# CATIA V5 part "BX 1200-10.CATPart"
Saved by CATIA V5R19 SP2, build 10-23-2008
Part number: BX 1200-10
Bounding box of the stored display mesh (mm): x -59.975 to 59.975, y -59.975 to 59.975, z 0 to 100
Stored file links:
  C:\Users\Bora\Desktop\3D Katı model\BX serisi\BX 1200\BX 1200-10.CATPart
  C:\Program Files\Dassault Systemes\B19\intel_a\reffiles\standard\MetricThickPitch.txt
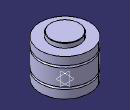
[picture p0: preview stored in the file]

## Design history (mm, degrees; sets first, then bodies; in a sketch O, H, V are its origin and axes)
Body1 (main body)
  Sketch1 on yz-plane, origin (0, 0, 0), H (0, 1, 0), V (0, 0, 1)
    point P2 (60, 20)
    line L1 (60, 20) -> (60, 0)
    point P3 (60, 25)
    point P4 (60, 65)
    line L2 (60, 65) -> (60, 25)
    point P6 (35, 99)
    arc A1 centre (34, 99) radius 1 from (35, 99) to (34, 100) ccw
    point P8 (35, 99)
    line L3 (35, 99) -> (35, 89)
    point P9 (60, 70)
    line L4 (60, 89) -> (60, 70)
    point P11 (60, 20)
    point P12 (60, 25)
    arc A2 centre (60, 22.5) radius 2.5 from (60, 25) to (60, 20) ccw
    point P13 (60, 65)
    point P14 (60, 70)
    arc A3 centre (60, 67.5) radius 2.5 from (60, 70) to (60, 65) ccw
    line L5 (34, 100) -> (0, 100)
    point P15 (0, 100)
    line L6 (35, 89) -> (60, 89)
    line L7 (60, 0) -> (0, 0)
    tangency: L5 A1
    coincidence: P15 V, P2 P11, P3 P12, P4 P13, P6 P8, P9 P14
    horizontal: L6 H, L7 H
  Shaft1: profile Sketch1, axis Sketch1.V, angle 360
  Sketch2 on face of Shaft1 from Sketch1.L7, origin (0, 0, 0), H (1, 0, 0), V (0, -1, 0)
    point P1 (32.5, 0)
    distance P1 V = 32.5
  Hole1: placed by Sketch2, at (32.5, 0, 0) direction (0, 0, 1), diameter 8.376, depth 10, threaded "M10", thread diameter 10, thread depth 10, pitch 1.5
  CircPattern1: of Hole1, instances 4, angular step 90, axis from xy-plane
